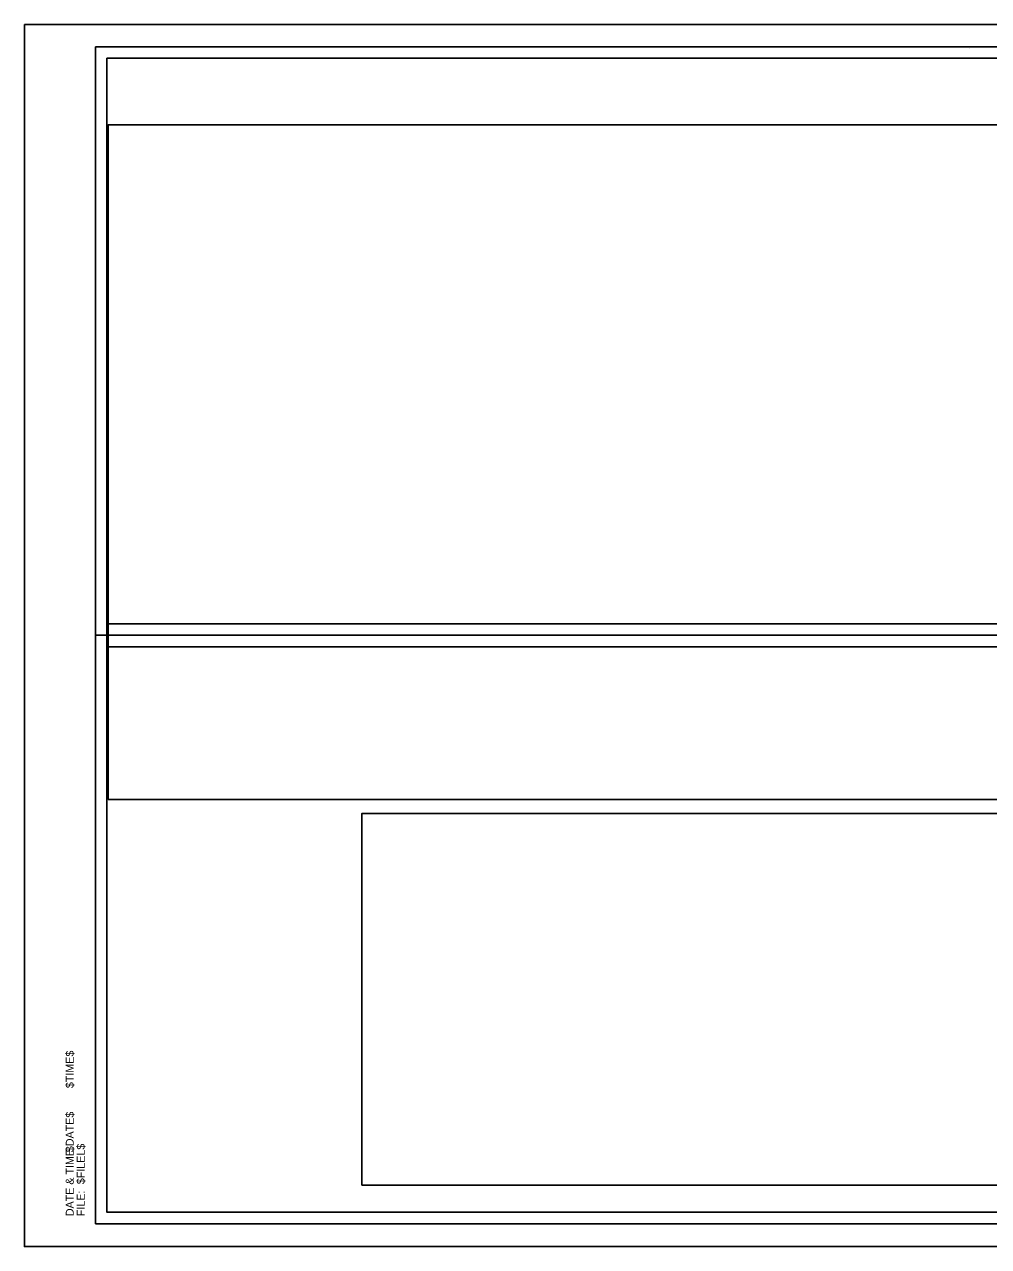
# Model space of a CAD drawing. Extents: x 1369904 to 1372237, y 380119 to 380332.
# Drawn here: x 1369903.6 to 1370071.9, y 380119.1 to 380332.4 of the extents above; entities that cross this region are included whole.
import ezdxf

# ---------------------------------------------------------------- set-up
doc = ezdxf.new("R2010")
doc.units = 0
for name, color, linetype in [('Default', 7, 'Continuous'), ('R_Border', 7, 'Continuous'), ('R_Border Notes', 7, 'Continuous'), ('R_Border Plan-Plan', 7, 'Continuous'), ('R_No Plot', 7, 'Continuous')]:
    doc.layers.add(name, color=color, linetype=linetype)

msp = doc.modelspace()

# ---------------------------------------------------------------- linework, layer by layer
at = {"layer": 'Default'}
for points in [[(1369918.18, 380197.09), (1370209.24, 380197.09), (1370209.24, 380314.85), (1369918.18, 380314.85)], [(1369962.47, 380129.75), (1370185.72, 380129.75), (1370185.72, 380194.65), (1369962.47, 380194.65)]]:
    msp.add_lwpolyline(points, close=True, dxfattribs=at)
at = {"layer": 'R_Border'}
for p, q in [((1369916, 380328.5), (1370232.18, 380328.5)), ((1369916, 380123.04), (1369916, 380328.5)), ((1370068.52, 380328.24), (1370068.52, 380328.24)), ((1370068.52, 380328.24), (1370068.52, 380328.24)), ((1369916, 380123.04), (1369916, 380123.04)), ((1370232.18, 380123.04), (1369916, 380123.04))]:
    msp.add_line(p, q, dxfattribs=at)
at = {"layer": 'R_Border Plan-Plan'}
msp.add_line((1369916, 380225.77), (1370232.18, 380225.77), dxfattribs=at)
at = {"layer": 'R_No Plot'}
for points in [[(1369903.6, 380332.4), (1370236.94, 380332.4), (1370236.94, 380119.06), (1369903.6, 380119.06)], [(1370230.18, 380227.77), (1369918, 380227.77), (1369918, 380326.5), (1370167.54, 380326.5), (1370167.54, 380316.62), (1370185.08, 380316.62), (1370209.18, 380316.62), (1370209.18, 380294.29), (1370230.18, 380294.29)], [(1369918, 380326.5), (1370167.54, 380326.5), (1370167.54, 380316.62), (1370185.08, 380316.62), (1370209.18, 380316.62), (1370209.18, 380294.29), (1370230.18, 380294.29), (1370230.18, 380125.04), (1369918, 380125.04)], [(1369918, 380223.77), (1370230.18, 380223.77), (1370230.18, 380125.04), (1369918, 380125.04)]]:
    msp.add_lwpolyline(points, close=True, dxfattribs=at)

# ---------------------------------------------------------------- texts
at = {"layer": 'R_Border Notes'}
for s, height, p in [('$TIME$', 1.397, (1369912.2, 380146.72)), ('$DATE$', 1.397, (1369912.2, 380135.54)), ('DATE & TIME:', 1.3968, (1369912.2, 380124.37)), ('$FILEL$', 1.397, (1369914.12, 380129.95)), ('FILE: ', 1.397, (1369914.12, 380124.37))]:
    msp.add_text(s, height=height, rotation=90, dxfattribs=at).set_placement(p)

doc.saveas('drawing.dxf')
